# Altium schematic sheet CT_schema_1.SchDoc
size 484 x 479 mm
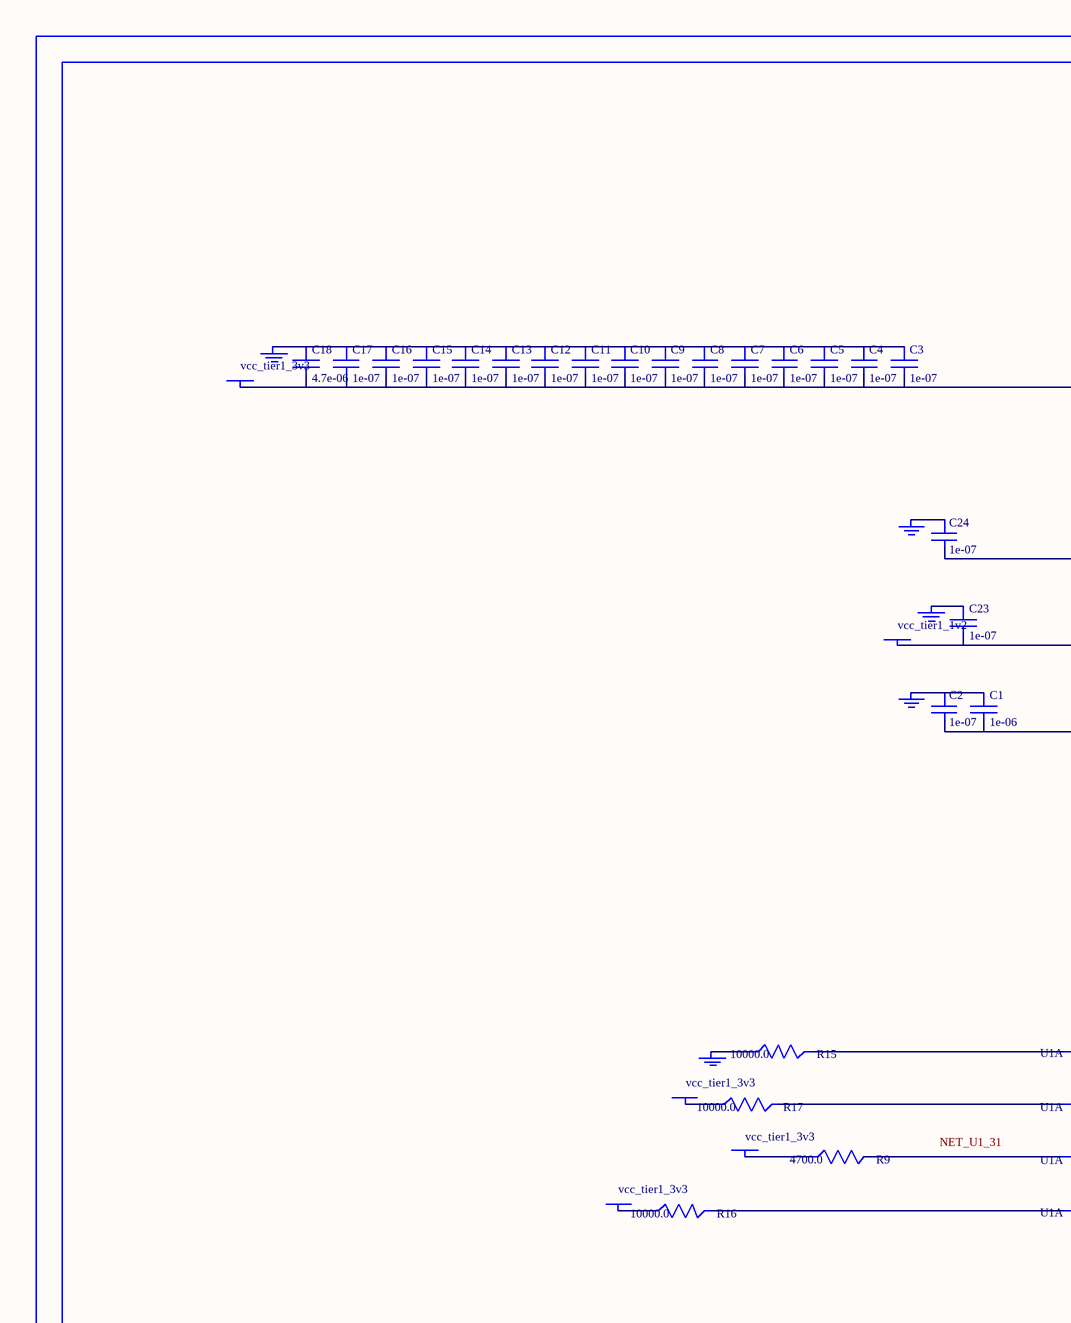
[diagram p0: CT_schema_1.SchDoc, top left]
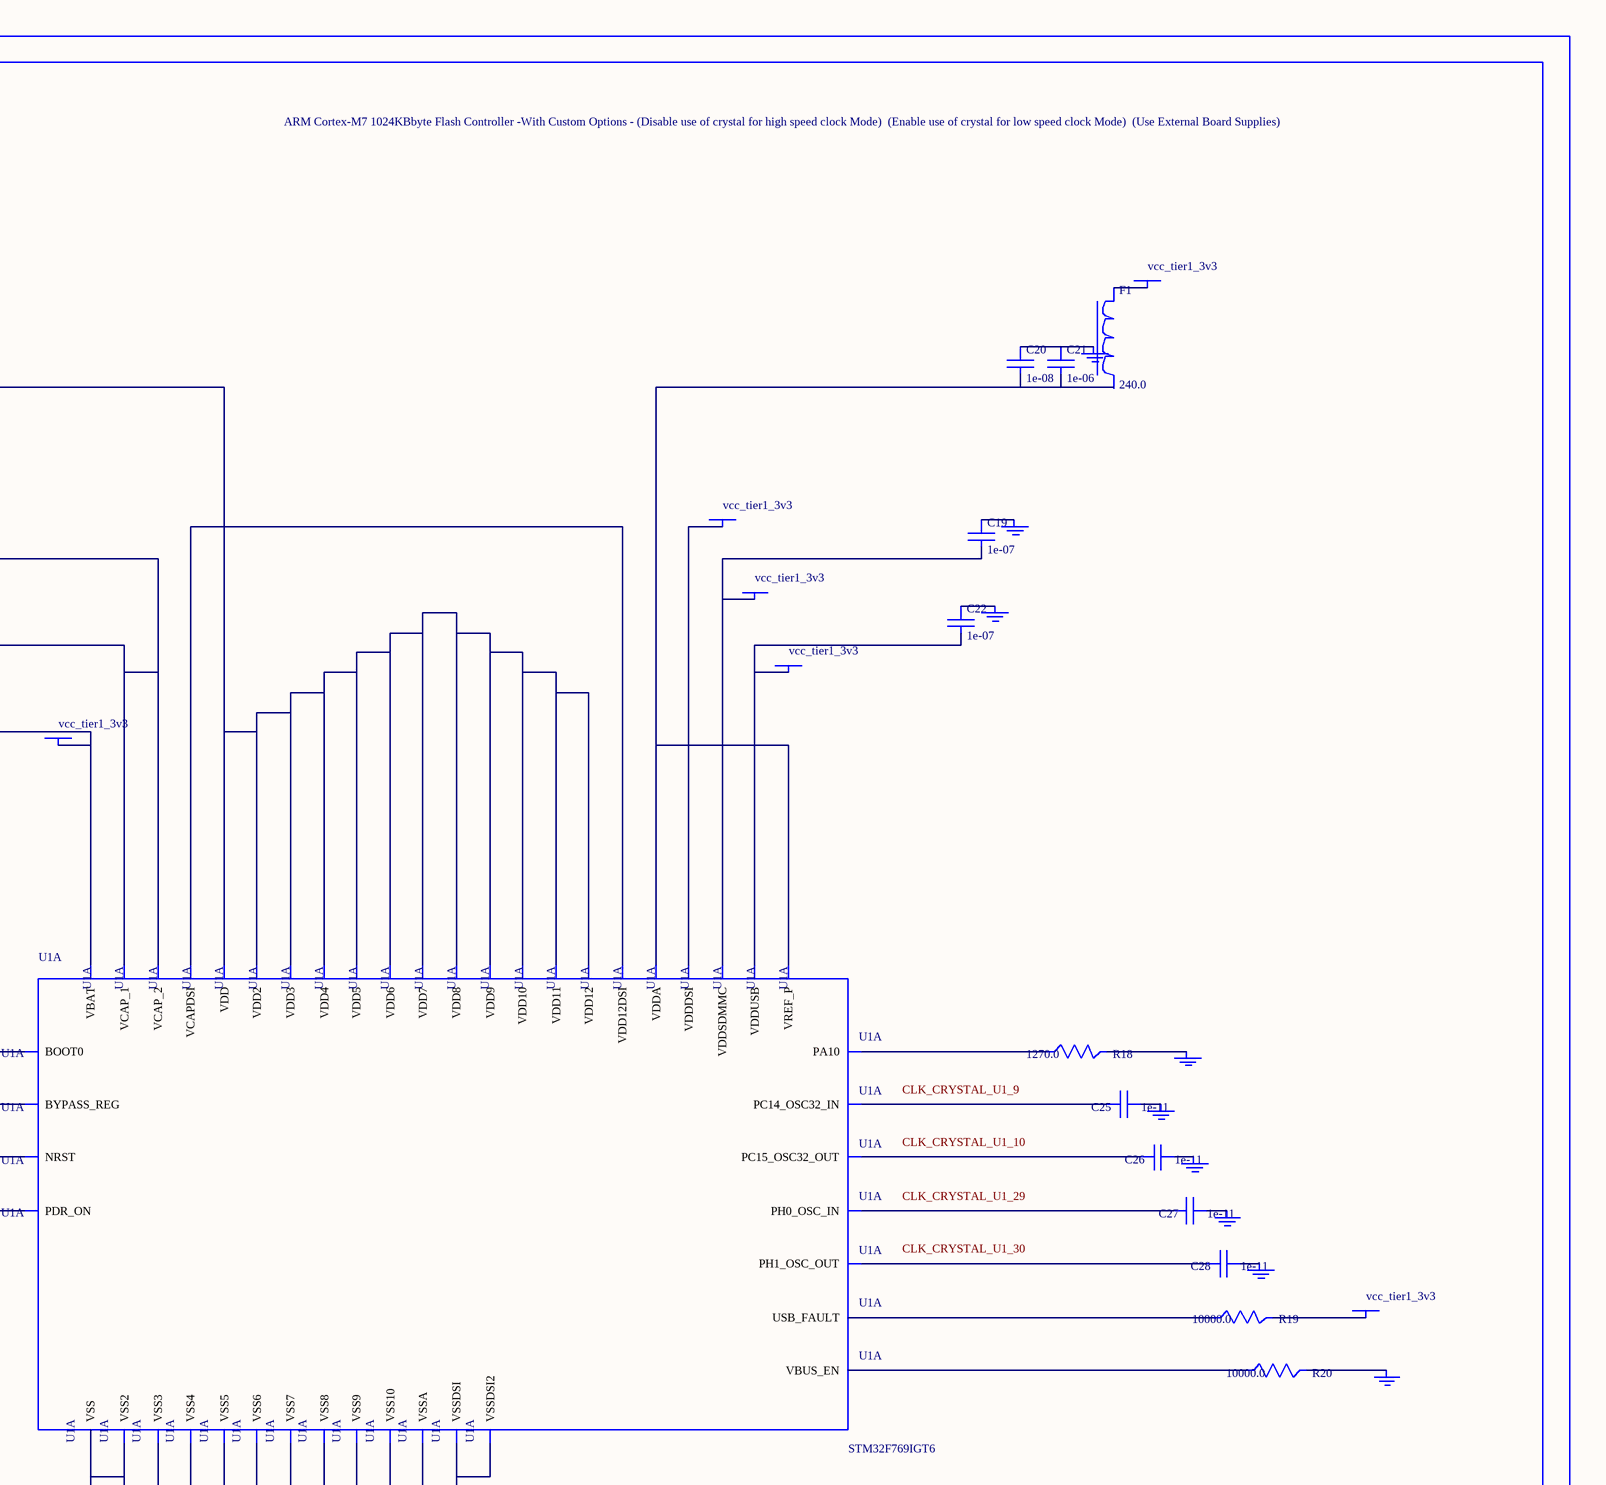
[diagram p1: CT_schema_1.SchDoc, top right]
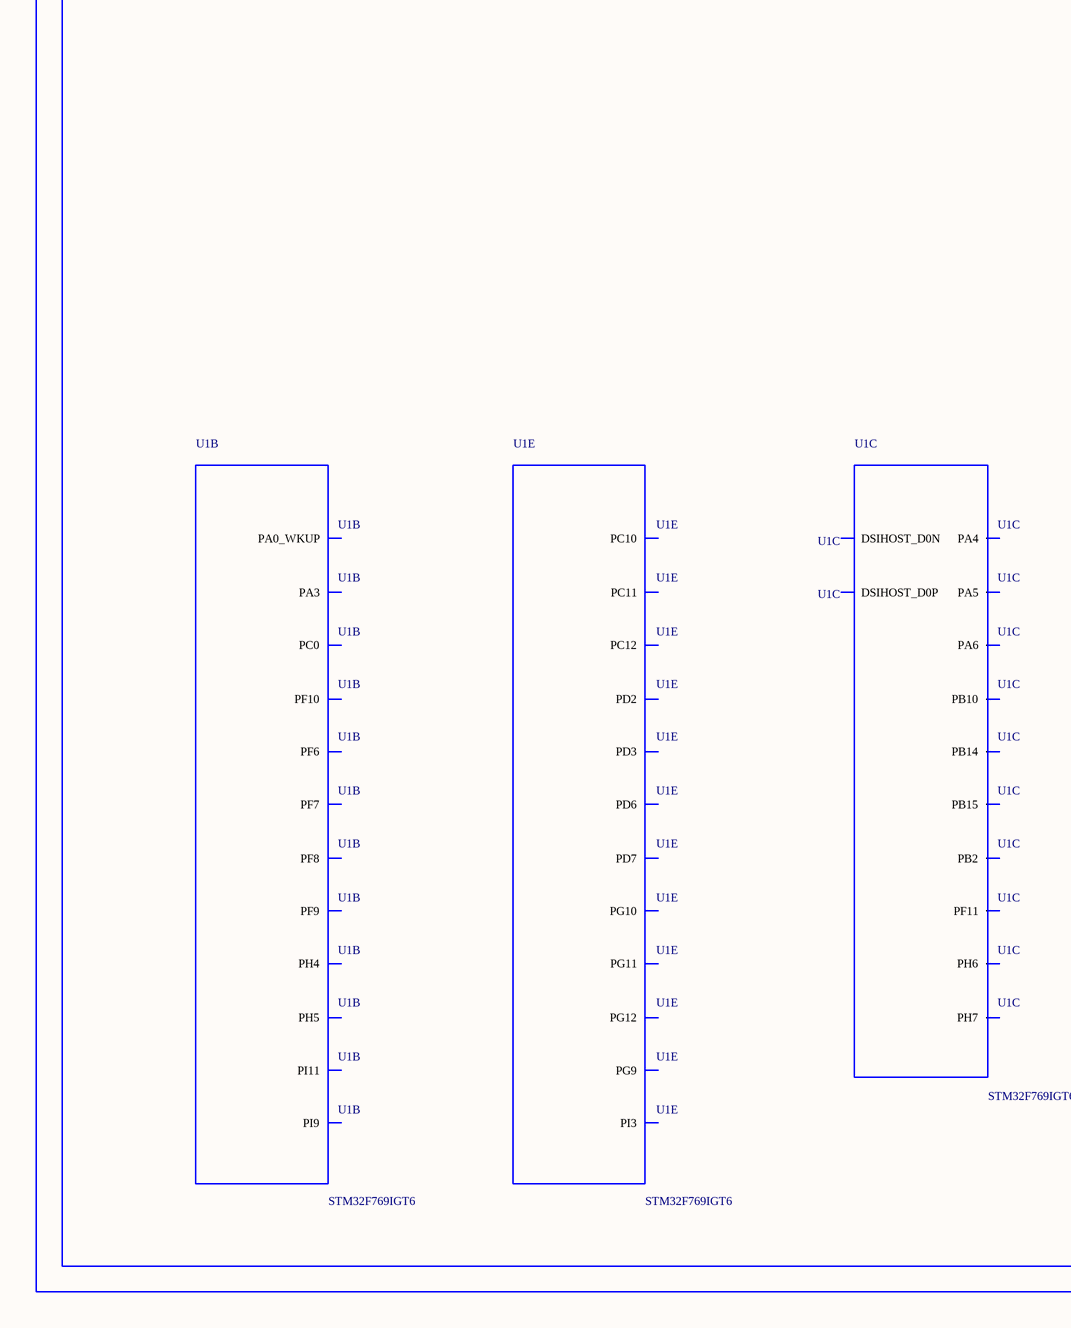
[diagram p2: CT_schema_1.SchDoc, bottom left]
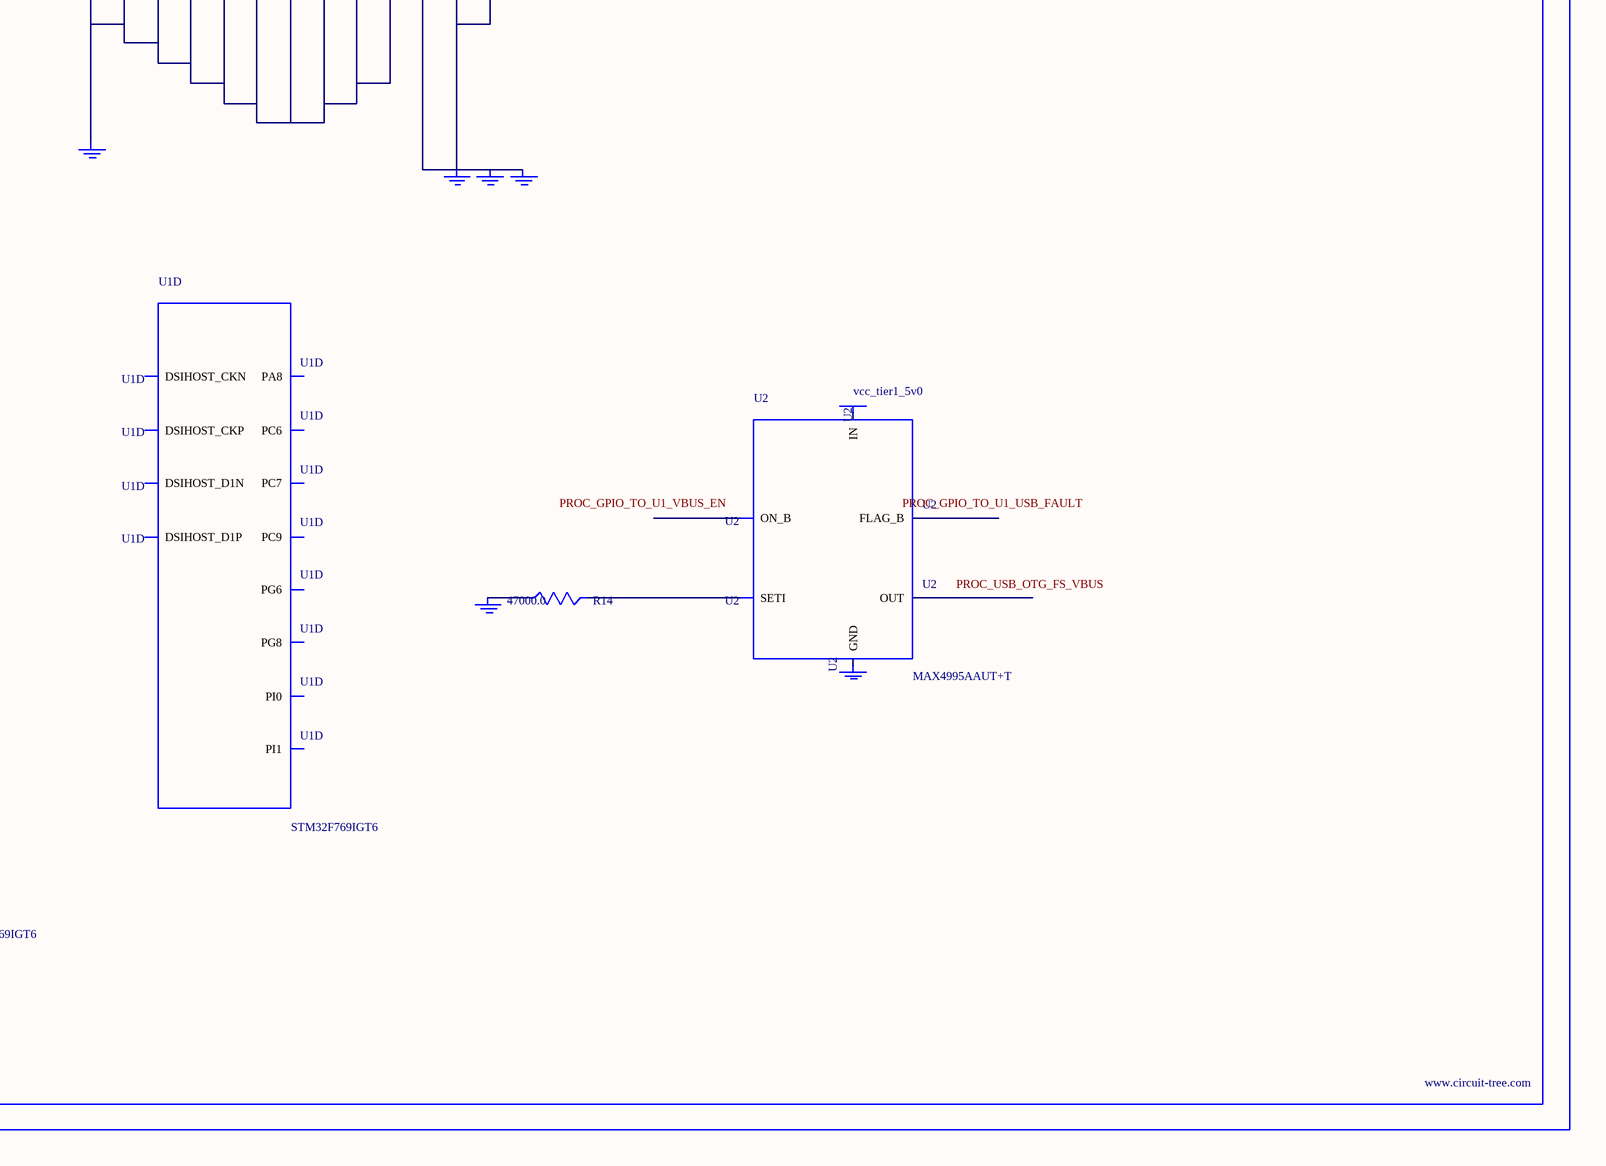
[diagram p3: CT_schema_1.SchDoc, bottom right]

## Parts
BORDER0  (no value)
C1  1e-06  [C0603]
C2  1e-07  [C0603]
C3  1e-07  [C0603]
C4  1e-07  [C0603]
C5  1e-07  [C0603]
C6  1e-07  [C0603]
C7  1e-07  [C0603]
C8  1e-07  [C0603]
C9  1e-07  [C0603]
C10  1e-07  [C0603]
C11  1e-07  [C0603]
C12  1e-07  [C0603]
C13  1e-07  [C0603]
C14  1e-07  [C0603]
C15  1e-07  [C0603]
C16  1e-07  [C0603]
C17  1e-07  [C0603]
C18  4.7e-06  [C0603]
C19  1e-07  [C0603]
C20  1e-08  [C0603]
C21  1e-06  [C0603]
C22  1e-07  [C0603]
C23  1e-07  [C0603]
C24  1e-07  [C0603]
C25  1e-11  [C0402]
C26  1e-11  [C0402]
C27  1e-11  [C0402]
C28  1e-11  [C0402]
F1  240.0  [L0603]
GND_INSTANCE_0_0  (no value)
GND_INSTANCE_0_1  (no value)
GND_INSTANCE_0_2  (no value)
GND_INSTANCE_0_3  (no value)
GND_INSTANCE_0_4  (no value)
GND_INSTANCE_0_5  (no value)
GND_INSTANCE_0_6  (no value)
GND_INSTANCE_0_7  (no value)
GND_INSTANCE_0_8  (no value)
GND_INSTANCE_0_9  (no value)
GND_INSTANCE_0_10  (no value)
GND_INSTANCE_0_11  (no value)
GND_INSTANCE_0_12  (no value)
GND_INSTANCE_0_13  (no value)
GND_INSTANCE_0_14  (no value)
GND_INSTANCE_0_15  (no value)
GND_INSTANCE_0_16  (no value)
GND_INSTANCE_0_17  (no value)
GND_INSTANCE_0_18  (no value)
GND_INSTANCE_0_19  (no value)
POWER_INSTANCE_0_0  vcc_tier1_3v3
POWER_INSTANCE_0_1  vcc_tier1_3v3
POWER_INSTANCE_0_2  vcc_tier1_3v3
POWER_INSTANCE_0_3  vcc_tier1_3v3
POWER_INSTANCE_0_4  vcc_tier1_3v3
POWER_INSTANCE_0_5  vcc_tier1_1v2
POWER_INSTANCE_0_6  vcc_tier1_3v3
POWER_INSTANCE_0_7  vcc_tier1_3v3
POWER_INSTANCE_0_8  vcc_tier1_3v3
POWER_INSTANCE_0_9  vcc_tier1_3v3
POWER_INSTANCE_0_10  vcc_tier1_3v3
POWER_INSTANCE_0_11  vcc_tier1_5v0
R9  4700.0  [R0603]
R14  47000.0  [R0603]
R15  10000.0  [R0603]
R16  10000.0  [R0603]
R17  10000.0  [R0603]
R18  1270.0  [R0603]
R19  10000.0  [R0603]
R20  10000.0  [R0603]
U1  STM32F769IGT6  [LQFP176]  (parts A,B,C,D,E of 13)
U2  MAX4995AAUT+T  [SOT-23-6]

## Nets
NetC1_1: C1.1 C2.1 GND_INSTANCE_0_0.0(GND)
NetC1_2: C1.2 C2.2 POWER_INSTANCE_0_0.0(PWR) U1.6(VBAT)
NetC3_1: C3.1 C4.1 C5.1 C6.1 C7.1 C8.1 C9.1 C10.1 C11.1 C12.1 C13.1 C14.1 C15.1 C16.1 C17.1 C18.1 GND_INSTANCE_0_4.0(GND)
NetC3_2: C3.2 C4.2 C5.2 C6.2 C7.2 C8.2 C9.2 C10.2 C11.2 C12.2 C13.2 C14.2 C15.2 C16.2 C17.2 C18.2 POWER_INSTANCE_0_2.0(PWR) U1.15(VDD) U1.23(VDD2) U1.36(VDD3) U1.49(VDD4) U1.62(VDD5) U1.72(VDD6) U1.82(VDD7) U1.96(VDD8) U1.131(VDD9) U1.136(VDD10) U1.159(VDD11) U1.172(VDD12)
NetC19_1: C19.1 GND_INSTANCE_0_15.0(GND)
NetC19_2: C19.2 POWER_INSTANCE_0_8.0(PWR) U1.149(VDDSDMMC)
NetC20_1: C20.1 C21.1 GND_INSTANCE_0_8.0(GND)
NetC20_2: C20.2 C21.2 U1.38(VREF_P) U1.39(VDDA)
NetC22_1: C22.1 GND_INSTANCE_0_12.0(GND)
NetC22_2: C22.2 POWER_INSTANCE_0_7.0(PWR) U1.118(VDDUSB)
NetC23_1: C23.1 GND_INSTANCE_0_9.0(GND)
NetC23_2: C23.2 C24.2 POWER_INSTANCE_0_5.0(PWR) U1.81(VCAP_1) U1.129(VCAP_2)
NetC24_1: C24.1 GND_INSTANCE_0_14.0(GND)
NetC25_1: C25.1 GND_INSTANCE_0_2.0(GND)
NetC25_2: C25.2 U1.9(PC14_OSC32_IN)
NetC26_1: C26.1 GND_INSTANCE_0_3.0(GND)
NetC26_2: C26.2 U1.10(PC15_OSC32_OUT)
NetC27_1: C27.1 GND_INSTANCE_0_5.0(GND)
NetC27_2: C27.2 U1.29(PH0_OSC_IN)
NetC28_1: C28.1 GND_INSTANCE_0_6.0(GND)
NetC28_2: C28.2 U1.30(PH1_OSC_OUT)
NetF1_1: F1.1 POWER_INSTANCE_0_3.0(PWR)
NetGND_INSTANCE_0_1_0: GND_INSTANCE_0_1.0(GND) R20.2
NetGND_INSTANCE_0_7_0: GND_INSTANCE_0_7.0(GND) GND_INSTANCE_0_10.0(GND) GND_INSTANCE_0_11.0(GND) U1.37(VSSA) U1.103(VSSDSI) U1.109(VSSDSI2)
NetGND_INSTANCE_0_13_0: GND_INSTANCE_0_13.0(GND) R18.2
NetGND_INSTANCE_0_16_0: GND_INSTANCE_0_16.0(GND) R15.1
NetGND_INSTANCE_0_17_0: GND_INSTANCE_0_17.0(GND) U1.14(VSS) U1.22(VSS2) U1.61(VSS3) U1.71(VSS4) U1.95(VSS5) U1.117(VSS6) U1.130(VSS7) U1.135(VSS8) U1.148(VSS9) U1.158(VSS10)
NetGND_INSTANCE_0_18_0: GND_INSTANCE_0_18.0(GND) R14.1
NetPOWER_INSTANCE_0_1_0: POWER_INSTANCE_0_1.0(PWR) R19.2
NetPOWER_INSTANCE_0_4_0: POWER_INSTANCE_0_4.0(PWR) R17.1
NetPOWER_INSTANCE_0_6_0: POWER_INSTANCE_0_6.0(PWR) U1.99(VDDDSI)
NetPOWER_INSTANCE_0_9_0: POWER_INSTANCE_0_9.0(PWR) R16.1
NetPOWER_INSTANCE_0_10_0: POWER_INSTANCE_0_10.0(PWR) R9.1
NetR9_2: R9.2 U1.31(NRST)
NetR14_2: R14.2 U2.3(SETI)
NetR15_2: R15.2 U1.166(BOOT0)
NetR16_2: R16.2 U1.171(PDR_ON)
NetR17_2: R17.2 U1.48(BYPASS_REG)
NetR18_1: R18.1 U1.125(PA10)
NetR19_1: R19.1 U1.8(USB_FAULT)
NetR20_1: R20.1 U1.7(VBUS_EN)
NetU1_100: U1.100(VCAPDSI) U1.106(VDD12DSI)

Not connected (* = marked no-connect by the designer): F1 2; GND_INSTANCE_0_19 0(GND); POWER_INSTANCE_0_11 0(PWR); U1 11(PI9) 13(PI11) 24(PF6) 25(PF7) 26(PF8) 27(PF9) 28(PF10) 32(PC0) 40(PA0_WKUP) 45(PH4) 46(PH5) 47(PA3) 50(PA4) 51(PA5) 52(PA6) 58(PB2) 59(PF11) 79(PB10) 83(PH6) 84(PH7) 87(PB14) 88(PB15) 101(DSIHOST_D0P) 102(DSIHOST_D0N) 104(DSIHOST_CKP) 105(DSIHOST_CKN) 107(DSIHOST_D1P) 108(DSIHOST_D1N) 114(PG6) 116(PG8) 119(PC6) 120(PC7) 122(PC9) 123(PA8) 132(PI0) 133(PI1) 134(PI3) 139(PC10) 140(PC11) 141(PC12) 144(PD2) 145(PD3) 150(PD6) 151(PD7) 152(PG9) 153(PG10) 154(PG11) 155(PG12); U2 1(OUT) 2(GND) 4(ON_B) 5(IN) 6(FLAG_B)

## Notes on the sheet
- Labels drawn without touching a wire or pin: CLK_CRYSTAL_U1_9, CLK_CRYSTAL_U1_10, CLK_CRYSTAL_U1_29, CLK_CRYSTAL_U1_30, NET_U1_31, PROC_GPIO_TO_U1_USB_FAULT, PROC_GPIO_TO_U1_VBUS_EN, PROC_USB_OTG_FS_VBUS

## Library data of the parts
BORDER0 = BORDER_PAGE0
C1 C21 = C0603C105K3RACTU
C2-C17 C19 C22-C24 = 06035C104K4Z2A
C18 = GRM188R6YA475KE15D
C20 = 06035C103K4Z2A
C25-C28 = C0402C100K3GACTU
F1 = Z0603C241ASMST
GND_INSTANCE_0_0-GND_INSTANCE_0_19 = GND
POWER_INSTANCE_0_0-POWER_INSTANCE_0_11 = PWR
R9 = RC0603JR-074K7L
R14 = RC0603JR-0747KL
R15-R17 R19 R20 = RC0603JR-0710KL
R18 = RC0603FR-071K27L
